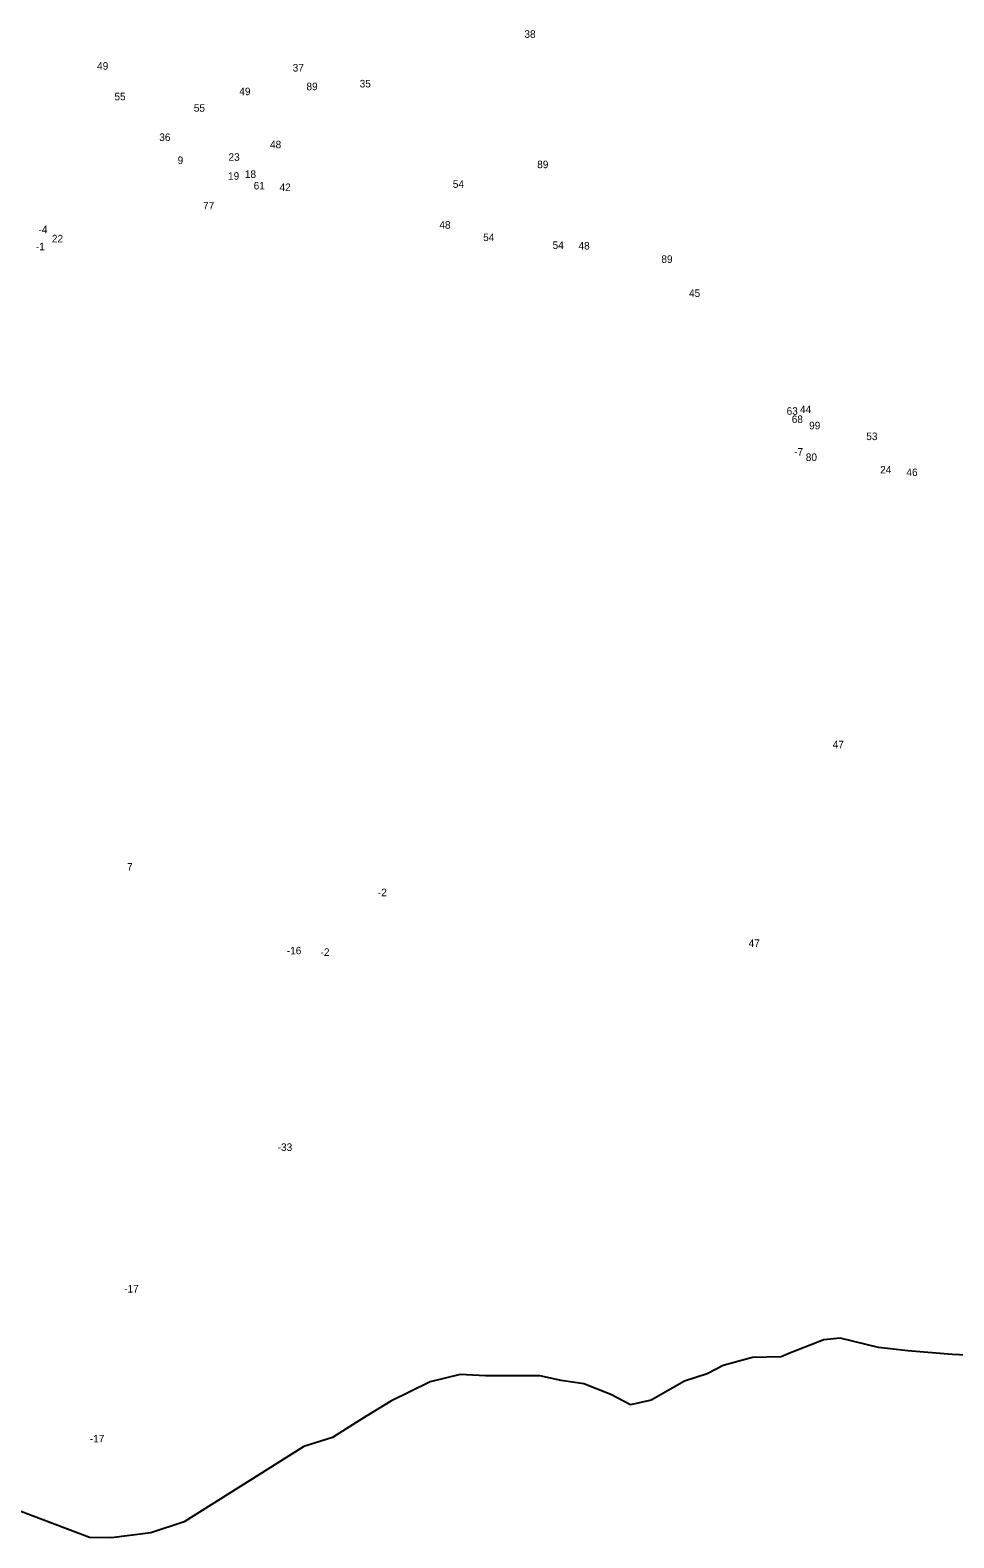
# Model space of a CAD drawing. Extents: x -772472 to -767535, y -969581 to -965387.
# Drawn here: x -771228 to -770002, y -969579 to -967578 of the extents above; entities that cross this region are included whole.
import ezdxf

# ---------------------------------------------------------------- set-up
doc = ezdxf.new("R2010")
doc.units = 0
doc.layers.add('Vrstva 13', color=7, linetype='Continuous')
doc.layers.add('Vrstva 24', color=7, linetype='Continuous')

msp = doc.modelspace()

# ---------------------------------------------------------------- linework, layer by layer
at = {"layer": 'Vrstva 13'}
for p, q in [((-770174.29, -969316.03), (-770218.6, -969333.22)), ((-770152.59, -969313.77), (-770174.29, -969316.03)), ((-770101.96, -969326.43), (-770152.59, -969313.77)), ((-770063.08, -969330.5), (-770101.96, -969326.43)), ((-770004.3, -969335.48), (-770063.08, -969330.5)), ((-770308.11, -969349.96), (-770329.36, -969361.26)), ((-770269.23, -969339.55), (-770308.11, -969349.96)), ((-770231.26, -969338.64), (-770269.23, -969339.55)), ((-770218.6, -969333.22), (-770231.26, -969338.64)), ((-769965.87, -969337.29), (-770004.3, -969335.48)), ((-770696.91, -969371.67), (-770749.35, -969397.45)), ((-770657.12, -969362.17), (-770696.91, -969371.67)), ((-770623.67, -969363.98), (-770657.12, -969362.17)), ((-770551.33, -969363.98), (-770623.67, -969363.98)), ((-770523.3, -969369.86), (-770551.33, -969363.98)), ((-770493.01, -969374.38), (-770523.3, -969369.86)), ((-770359.2, -969370.76), (-770403.5, -969396.09)), ((-770329.36, -969361.26), (-770359.2, -969370.76)), ((-770457.3, -969388.4), (-770493.01, -969374.38)), ((-770431.08, -969402.42), (-770457.3, -969388.4)), ((-770749.35, -969397.45), (-770786.88, -969420.52)), ((-770403.5, -969396.09), (-770431.08, -969402.42)), ((-770786.88, -969420.52), (-770826.66, -969445.84)), ((-770826.66, -969445.84), (-770864.64, -969457.6)), ((-770864.64, -969457.6), (-771023.33, -969557.55)), ((-771149.02, -969578.36), (-771286.45, -969526.35)), ((-771067.64, -969572.02), (-771120.08, -969578.81)), ((-771023.33, -969557.55), (-771067.64, -969572.02)), ((-771120.08, -969578.81), (-771149.02, -969578.36))]:
    msp.add_line(p, q, dxfattribs=at)

# ---------------------------------------------------------------- texts
at = {"layer": 'Vrstva 24'}
for s, p in [('38', (-770571.916, -967588.19)), ('49', (-771139.066, -967630.5)), ('37', (-770879.456, -967632.9)), ('89', (-770861.18, -967657.74)), ('35', (-770790.586, -967654.06)), ('55', (-771116.066, -967671.07)), ('49', (-770950.316, -967664.32)), ('55', (-771010.696, -967686.29)), ('36', (-771056.55, -967725.15)), ('48', (-770909.532, -967734.78)), ('9', (-771032.13, -967755.69)), ('23', (-770964.646, -967751.41)), ('89', (-770554.92, -967761.19)), ('19', (-770965.254, -967776.58)), ('18', (-770942.971, -967774.14)), ('61', (-770931.264, -967789.44)), ('42', (-770896.912, -967791.53)), ('54', (-770666.922, -967787.34)), ('77', (-770998.414, -967816.04)), ('48', (-770684.782, -967841.58)), ('-4', (-771216.846, -967847.55)), ('22', (-771199.056, -967859.65)), ('54', (-770626.632, -967857.94)), ('-1', (-771220.364, -967870.17)), ('54', (-770534.502, -967868.37)), ('48', (-770500.092, -967869.13)), ('89', (-770390.1, -967886.9)), ('45', (-770353.422, -967932.06)), ('63', (-770223.86, -968088.45)), ('68', (-770217.11, -968099.38)), ('44', (-770206.128, -968086.27)), ('99', (-770194.004, -968107.67)), ('53', (-770118.136, -968122.04)), ('-7', (-770213.899, -968142.66)), ('80', (-770198.416, -968149.73)), ('24', (-770099.702, -968166.36)), ('46', (-770064.896, -968169.75)), ('47', (-770162.681, -968530.95)), ('7', (-771099.346, -968693.29)), ('-2', (-770766.4, -968727.32)), ('47', (-770274.281, -968794.78)), ('-16', (-770887.288, -968804.56)), ('-2', (-770842.46, -968806.54)), ('-33', (-770899.35, -969065.34)), ('-17', (-771103.094, -969253.28)), ('-17', (-771148.734, -969452.28))]:
    msp.add_text(s, height=10, dxfattribs=at).set_placement(p)

doc.saveas('drawing.dxf')
